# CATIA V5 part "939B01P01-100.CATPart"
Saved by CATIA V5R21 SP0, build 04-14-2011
Part number: 939B01P01-100
Bounding box of the stored display mesh (mm): x -17.1 to 17.1, y -76.2 to 76.2, z -4.4 to 95.6
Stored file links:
  C:\Users\ALI OZGUN\Desktop\alhan\TESLIMEDILEN3\939B01P01-100.CATPart
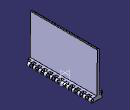
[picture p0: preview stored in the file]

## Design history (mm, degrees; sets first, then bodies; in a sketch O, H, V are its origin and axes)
Body1 (main body)
  Sketch1 on zx-plane, origin (0, 0, 0), H (-1, 0, 0), V (0, 0, 1)
    construction line L1 (-12.7, 0) -> (12.7, 0)
    point P1 (-12.7, 0)
    line L2 (-12.7, 4.4) -> (12.7, 4.4)
    line L3 (12.7, -4.4) -> (-12.7, -4.4)
    arc A1 centre (12.7, 0) radius 4.4 from (12.7, 4.4) to (12.7, -4.4) cw
    arc A2 centre (-12.7, 0) radius 4.4 from (-12.7, -4.4) to (-12.7, 4.4) cw
    distance L1 L2 = 4.4
    length L1 = 25.4
    distance P1 V = 12.7
    coincidence: P1 H
    horizontal: L1 H
    tangency: A1 L2, A2 L2, A1 L3, A2 L3
  Pad1: profile Sketch1, direction (0, 1, 0), length 76.2, mirrored extent
  Sketch2 on face of Pad1 from Sketch1.L2, origin (0, 0, 4.4), H (1, 0, 0), V (0, 1, 0)
    line L1 (-22.3127, -63.5) -> (-9.75, -63.5)
    line L2 (-9.75, -63.5) -> (-9.75, -70.6)
    line L3 (-9.75, -70.6) -> (-22.3127, -70.6)
    line L4 (-22.3127, -70.6) -> (-22.3127, -63.5)
    line L5 (24.6678, -76.95) -> (9.75, -76.95)
    line L6 (9.75, -76.95) -> (9.75, -69.85)
    line L7 (9.75, -69.85) -> (24.6678, -69.85)
    line L8 (24.6678, -69.85) -> (24.6678, -76.95)
    reference projected line E1 (-12.7, -76.2) -> (12.7, -76.2) from edge [start face of Pad1 | face of Pad1 from Sketch1.L2]
    reference projected line E2 (-12.7, -76.2) -> (12.7, -76.2) from edge [start face of Pad1 | face of Pad1 from Sketch1.L2]
    distance L3 E1 = 5.6
    length L4 = 7.1
    distance L7 L5 = 7.1
    distance L5 E2 = 0.75
    distance L2 L6 = 19.5
    distance L2 V = 9.75
    horizontal: L1 H, L3 H, L5 H, L7 H
    vertical: L2 V, L4 V, L6 V, L8 V
  Pocket1: profile Sketch2, direction (0, 0, -1), length 76.2
  RectPattern1: of Pocket1, direction 1 instances 12, spacing 12.7, along axis of face of Pad1 from Sketch1.A2
  Sketch3 on face of Pad1 from Sketch1.L3, origin (0, 0, -4.4), H (1, 0, 0), V (0, -1, 0)
    line L1 (-6.5, -54.6) -> (6.5, -54.6)
    line L2 (6.5, -54.6) -> (6.5, -73.7)
    line L3 (6.5, -73.7) -> (-6.5, -73.7)
    line L4 (-6.5, -73.7) -> (-6.5, -54.6)
    construction line L5 (-4.5, -51.1) -> (4.5, -51.1)
    point P5 (-4.5, -51.1)
    line L6 (-4.5, -49.6) -> (4.5, -49.6)
    line L7 (4.5, -52.6) -> (-4.5, -52.6)
    arc A1 centre (4.5, -51.1) radius 1.5 from (4.5, -49.6) to (4.5, -52.6) cw
    arc A2 centre (-4.5, -51.1) radius 1.5 from (-4.5, -52.6) to (-4.5, -49.6) cw
    reference projected line E1 (12.7, -76.2) -> (-12.7, -76.2) from edge [face of Pad1 from Sketch1.L3 | end face of Pad1]
    distance L5 L6 = 1.5
    distance L1 L3 = 19.1
    distance L4 L2 = 13
    distance L4 V = 6.5
    distance E1 L3 = 2.5
    distance P5 V = 4.5
    length L5 = 9
    distance L7 L1 = 2
    horizontal: L1 H, L3 H, L5 H
    vertical: L2 V, L4 V
    tangency: A1 L6, A2 L6, A1 L7, A2 L7
  Pocket2: profile Sketch3, direction (0, 0, 1), length 6
  RectPattern2: of Pocket2, direction 1 instances 6, spacing 25.8, along axis of face of Pad1 from Sketch1.A2 reversed
  Sketch4 on zx-plane, origin (0, 0, 0), H (-1, 0, 0), V (0, 0, 1)
    circle A1 centre (12.7, 0) radius 2.3
    point P1 (12.7, 0)
    circle A2 centre (-12.7, 0) radius 2.3
    point P2 (-12.7, 0)
    reference projected arc E1 centre (12.7, 0) radius 4.4 from (12.7, -4.4) to (12.7, 4.4) ccw from edge [face of RectPattern1 | face of Pad1 from Sketch1.A1]
    reference projected arc E2 centre (-12.7, 0) radius 4.4 from (-12.7, 4.4) to (-12.7, -4.4) ccw from edge [face of Pad1 from Sketch1.A2 | end face of Pad1]
    radius A1 = 2.3
    radius A2 = 2.3
    coincidence: P1 H, P2 H
    concentricity: P1 E1, A2 E2
  Pocket3: profile Sketch4, direction (0, -1, 0), length 97.8, mirrored extent
  Body2
    Solid1: linked copy from another document
    Symmetry1: Reference yz-plane, ToTransfor Solid1
    Translate1: Direction edge [face of Pocket1 from Sketch2.L2 | face of Pad1 from Sketch1.L3], Length 6.35, ToTransfor Symmetry1
    Body3
      Sketch5 on face of RectPattern1, origin (9.75, 0, 0), H (0, 1, 0), V (0, 0, 1)
      Pad2: profile Sketch5, direction (1, 0, 0), length 12
      Sketch6 on face of Pad2, origin (0, 69.85, 0), H (-1, 0, 0), V (0, 0, 1)
        point P2 (-21.75, 4.4)
        arc A1 centre (-16.4898, 1.5645) radius 9 from (-9.75, -4.4) to (-7.9481, 4.4) ccw
        point P8 (-21.75, 4.4)
        construction line L1 (-9.75, 4.4) -> (-21.75, 4.4)
        line L2 (-7.9481, 4.4) -> (-21.75, 4.4)
        line L3 (-9.75, -4.4) -> (-21.75, -4.4)
        line L4 (-21.75, -4.4) -> (-21.75, 4.4)
        radius A1 = 9
        coincidence: P2 P8
      Pad3: profile Sketch6, direction (0, 1, 0), up to face of Pad2
      RectPattern3: of the body so far, direction 1 instances 12, spacing 12.7, along edge [face of Pad3 | face of Pad3] reversed
    Add1: tool Body3
  Remove1: tool Body2
  Sketch7 on zx-plane, origin (0, 0, 0), H (-1, 0, 0), V (0, 0, 1)
    projected line E1 (7.9481, 4.4) -> (-12.7, 4.4) from edge [face of Pad1 from Sketch1.L2 | end face of Pad1]
    projected line E2 (3.2, 4.4) -> (-3.2, 4.4) from edge [face of Pad1 from Sketch1.L2 | end face of Pad1]
    point P3 (-3.2, 4.4)
    line L1 (-3.2, 4.4) -> (-2, 95.6)
    point P4 (-2, 95.6)
    line L2 (-2, 95.6) -> (2, 95.6)
    line L3 (2, 95.6) -> (3.2, 4.4)
    reference projected line E3 (-12.7, -4.4) -> (12.7, -4.4) from edge [face of Pad1 from Sketch1.L3 | end face of Pad1]
    distance L2 E3 = 100
    distance P3 V = 3.2
    distance P4 V = 2
    coincidence: P3 E1, P3 L1
    horizontal: L2 H
    symmetry: L1 L3 V
  Pad4: profile Sketch7, direction (0, 1, 0), length 76.2, mirrored extent
  Fillet1: radius 1, on edge [face of Pad4 from Sketch7.L2 | face of Pad4 from Sketch7.L3]; edge [face of Pad4 from Sketch7.L1 | face of Pad4 from Sketch7.L2]
Body4
  Solid2: linked copy from another document
  Translate2: Direction yz-plane, Length 25.4, ToTransfor Solid2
